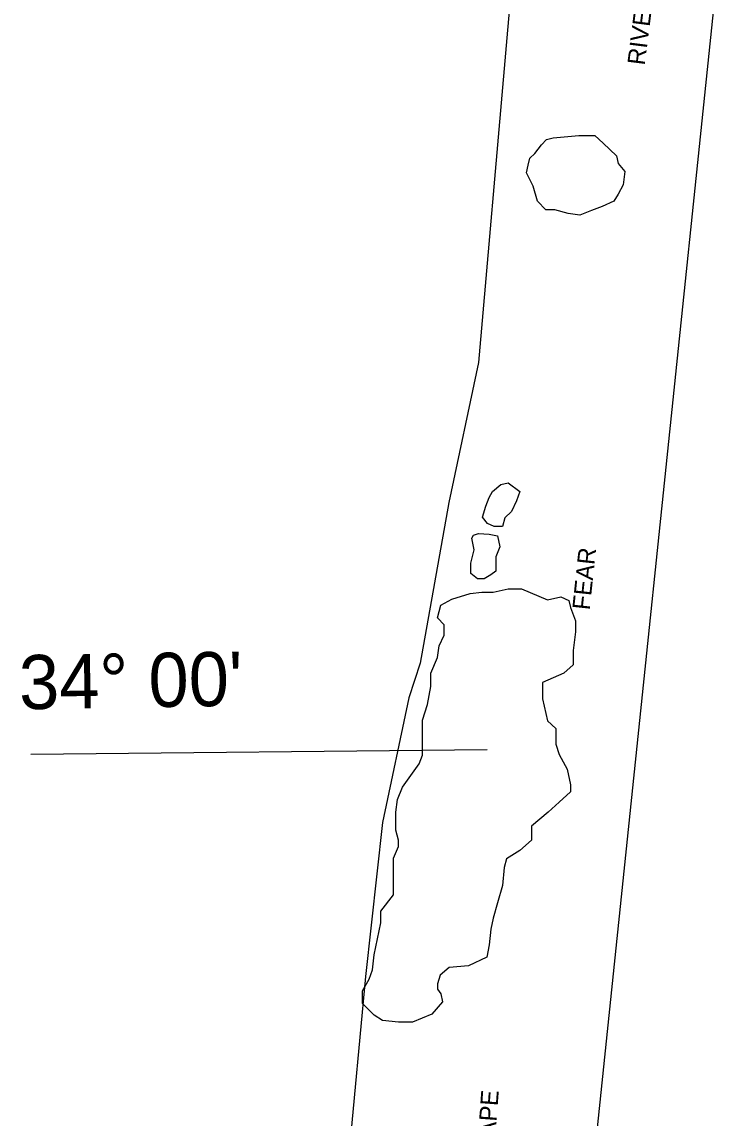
# Model space of a CAD drawing. Extents: x 2290055 to 2389491, y 66597 to 237875.
# Drawn here: x 2317385 to 2325869, y 88299 to 101465 of the extents above; entities that cross this region are included whole.
import ezdxf

# ---------------------------------------------------------------- set-up
doc = ezdxf.new("R2010")
doc.units = 0
for name, color, linetype in [('Exist Boundary Political CountyLine', 7, 'Continuous'), ('Exist Hydrographic Island Shore', 7, 'Continuous'), ('Exist Hydrographic River Shore Label', 7, 'Continuous'), ('Map Preparation Inset Cut Line', 7, 'Continuous'), ('Map Preparation Longitude Latitude Label', 7, 'Continuous'), ('Map Preparation Longitude Latitude Lines', 7, 'Continuous')]:
    doc.layers.add(name, color=color, linetype=linetype)

msp = doc.modelspace()

# ---------------------------------------------------------------- linework, layer by layer
at = {"layer": 'Exist Boundary Political CountyLine'}
msp.add_lwpolyline([(2322749, 125846), (2322867, 124334), (2323041, 122267), (2323614, 114667), (2323843, 108525), (2322871, 97375), (2322516, 95693), (2322171, 93762), (2322033, 93345), (2321718, 91849), (2321513, 90001), (2321309, 87812), (2321235, 87125), (2321141, 86736), (2320847, 85802), (2320228, 84678), (2318854, 82227)], dxfattribs=at)
at = {"layer": 'Exist Hydrographic Island Shore'}
for points in [[(2324088, 99145), (2323948, 99163), (2323788, 99210), (2323678, 99210), (2323579, 99313), (2323529, 99491), (2323449, 99651), (2323469, 99745), (2323489, 99829), (2323549, 99885), (2323628, 99988), (2323688, 100054), (2323768, 100073), (2324078, 100101), (2324268, 100101)], [(2324268, 100101), (2324368, 100007), (2324528, 99857), (2324548, 99763), (2324628, 99670), (2324608, 99510), (2324548, 99398), (2324498, 99313), (2324358, 99248), (2324228, 99201), (2324088, 99145)], [(2323229, 95929), (2323369, 95826), (2323329, 95714), (2323269, 95583), (2323189, 95508), (2323159, 95404), (2323059, 95404), (2322979, 95442), (2322919, 95517)], [(2322919, 95517), (2322959, 95648), (2322999, 95751), (2323039, 95826), (2323139, 95911), (2323229, 95929)], [(2322869, 95320), (2322999, 95311), (2323099, 95292), (2323129, 95161), (2323079, 95039), (2323079, 94945), (2323079, 94870), (2323019, 94823), (2322939, 94776), (2322859, 94776), (2322779, 94842), (2322779, 94964), (2322819, 95123)], [(2322819, 95123), (2322789, 95264), (2322809, 95301), (2322869, 95320)], [(2323698, 94523), (2323858, 94561), (2323958, 94514), (2323978, 94430), (2324038, 94270), (2324038, 94139), (2324008, 93914), (2324008, 93745), (2323898, 93642), (2323638, 93530), (2323638, 93333), (2323698, 93070), (2323798, 92977), (2323798, 92789), (2323838, 92667), (2323938, 92489), (2323978, 92302), (2323978, 92217), (2323838, 92095), (2323708, 91974), (2323509, 91805), (2323509, 91636), (2323369, 91514), (2323209, 91411), (2323179, 91308), (2323159, 91093), (2323099, 90886), (2323049, 90699), (2323019, 90568), (2322999, 90380), (2322969, 90230), (2322749, 90127), (2322519, 90108), (2322409, 90015), (2322379, 89911), (2322379, 89846), (2322419, 89790), (2322439, 89696), (2322309, 89546), (2322079, 89452), (2321909, 89452), (2321719, 89471), (2321619, 89536), (2321479, 89677), (2321479, 89827), (2321559, 89968), (2321599, 90080), (2321619, 90258), (2321679, 90549)], [(2321679, 90549), (2321699, 90643), (2321699, 90783), (2321849, 90980), (2321849, 91205), (2321849, 91289), (2321849, 91421), (2321909, 91561), (2321909, 91636), (2321879, 91758), (2321879, 91974), (2321899, 92124), (2321959, 92274), (2322059, 92414), (2322159, 92555), (2322199, 92658), (2322199, 92752), (2322199, 92911), (2322199, 93080), (2322259, 93267), (2322299, 93483), (2322299, 93642), (2322379, 93830), (2322399, 93970), (2322459, 94101), (2322459, 94223), (2322379, 94308), (2322419, 94458), (2322549, 94533), (2322769, 94598), (2322909, 94617), (2323049, 94617), (2323229, 94655), (2323389, 94655), (2323698, 94523)]]:
    msp.add_lwpolyline(points, dxfattribs=at)
at = {"layer": 'Map Preparation Inset Cut Line'}
msp.add_lwpolyline([(2327293, 115381), (2326421, 108601), (2323941, 84754), (2319662, 79548), (2319962, 76609), (2326694, 76609), (2329528, 82751), (2336452, 105361), (2339748, 115381)], close=True, dxfattribs=at)
at = {"layer": 'Map Preparation Longitude Latitude Lines'}
msp.add_line((2317492, 92670), (2322976, 92727), dxfattribs=at)

# ---------------------------------------------------------------- texts
at = {"layer": 'Exist Hydrographic River Shore Label'}
for s, rotation, p in [('RIVER', 82.785, (2324867, 100938)), ('FEAR', 83.9569, (2324206, 94395)), ('CAPE', 85.8251, (2323059, 87864))]:
    msp.add_text(s, height=210, rotation=rotation, dxfattribs=at).set_placement(p)
at = {"layer": 'Map Preparation Longitude Latitude Label'}
msp.add_text("34° 00'", height=650, rotation=0.9617, dxfattribs=at).set_placement((2317355, 93208))

doc.saveas('drawing.dxf')
